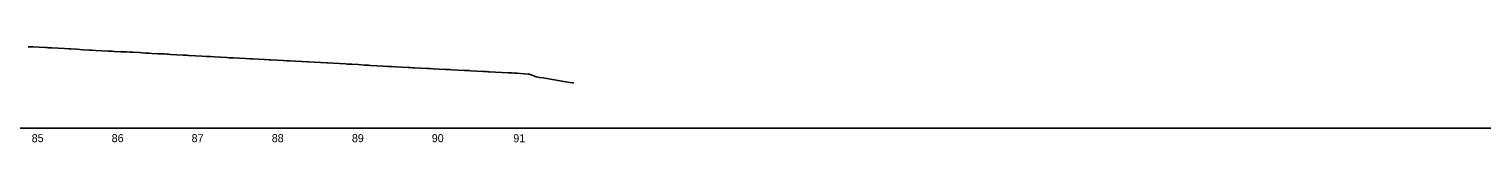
# Model space of a CAD drawing. Extents: x 579185 to 595036, y -53221 to -44640.
# Drawn here: x 586699 to 588514, y -46055 to -45936 of the extents above; entities that cross this region are included whole.
import ezdxf

# ---------------------------------------------------------------- set-up
doc = ezdxf.new("R2010")
doc.units = 0
for name, color, linetype in [('Exist Profile Cell', 7, 'Continuous'), ('Exist Vertical Profile Ground Line', 7, 'Continuous'), ('Exist Vertical Profile Horizontal Axis Label Major', 7, 'Continuous')]:
    doc.layers.add(name, color=color, linetype=linetype)

msp = doc.modelspace()

# ---------------------------------------------------------------- linework, layer by layer
at = {"layer": 'Exist Profile Cell'}
msp.add_line((579243, -46037.5), (595036.4, -46037.5), dxfattribs=at)
at = {"layer": 'Exist Vertical Profile Ground Line'}
for points in [[(586697.6, -45935.8), (586703.7, -45936.1), (586711.5, -45936.5), (586719.3, -45936.9), (586721.2, -45937), (586722.9, -45937.1), (586724.6, -45937.2), (586727.1, -45937.3), (586735, -45937.7), (586742.8, -45938.2), (586748.6, -45938.5), (586750.9, -45938.6), (586758.4, -45939), (586766.2, -45939.5), (586774.2, -45940), (586777.3, -45940.1), (586781.8, -45940.4), (586789.6, -45940.8), (586797.4, -45941.2), (586799.3, -45941.3), (586802.7, -45941.5), (586805.2, -45941.6), (586813, -45942), (586820.9, -45942.4), (586824.5, -45942.6), (586827.8, -45942.8), (586828.7, -45942.8), (586836.5, -45943.2), (586844.3, -45943.7), (586848.6, -45943.9), (586852.1, -45944.1), (586859.9, -45944.5), (586867.7, -45944.9), (586870.8, -45945.1), (586872.7, -45945.2), (586875.5, -45945.4), (586883.3, -45945.8), (586891.1, -45946.3), (586895.6, -45946.5), (586897.7, -45946.7), (586898.9, -45946.7), (586906.8, -45947.2), (586914.6, -45947.6), (586920.2, -45947.9), (586922.7, -45948.1), (586925.3, -45948.2), (586930.2, -45948.5), (586938, -45948.9), (586945.8, -45949.3), (586948.6, -45949.5), (586951.7, -45949.7), (586953.6, -45949.8), (586961.4, -45950.2), (586969.2, -45950.6), (586974.5, -45950.8), (586977, -45951)], [(586977, -45951), (586977.8, -45951), (586984.9, -45951.4), (586992.7, -45951.8), (586998.8, -45952.1), (587000.5, -45952.2), (587008.3, -45952.6), (587016.1, -45953), (587020.9, -45953.3), (587023, -45953.4), (587023.9, -45953.4), (587031.7, -45953.9), (587039.5, -45954.3), (587046.5, -45954.6), (587047.3, -45954.7), (587047.7, -45954.7), (587055.1, -45955.1), (587062.9, -45955.5), (587070.8, -45955.9), (587071.7, -45956), (587072.5, -45956), (587078.6, -45956.4), (587086.4, -45956.8), (587094.2, -45957.3), (587096.2, -45957.4), (587097.6, -45957.5), (587102, -45957.8), (587109.8, -45958.2), (587117.6, -45958.7), (587120.6, -45958.9), (587122.8, -45959), (587125.4, -45959.2), (587133.2, -45959.6), (587141, -45960), (587146.4, -45960.4), (587148.9, -45960.5), (587151.5, -45960.6), (587156.7, -45960.9), (587164.5, -45961.3), (587172.3, -45961.8), (587175.1, -45961.9), (587177.7, -45962.1), (587180.1, -45962.2), (587187.9, -45962.5), (587195.7, -45962.9), (587199.9, -45963.1), (587203.5, -45963.3), (587211.3, -45963.7), (587219.1, -45964.1), (587222.7, -45964.2), (587224.7, -45964.3), (587226.9, -45964.5), (587234.8, -45964.9), (587242.6, -45965.4), (587246.6, -45965.6), (587248.5, -45965.7), (587250.4, -45965.8), (587258.2, -45966.2), (587266, -45966.7), (587270.3, -45966.9), (587272.4, -45967.1), (587273.8, -45967.1), (587281.6, -45967.5), (587289.4, -45967.9), (587297.2, -45968.3), (587299.8, -45968.5), (587302.4, -45968.6), (587305, -45968.7), (587306.8, -45968.8), (587308.7, -45968.9), (587312.8, -45969.2), (587317.5, -45969.5), (587322.2, -45969.9), (587323.9, -45970), (587326.9, -45971.2), (587331.6, -45973.1), (587332.2, -45973.4), (587336.3, -45974.1), (587341, -45974.8), (587345.7, -45975.6), (587350.3, -45976.4), (587355, -45977.2), (587359.7, -45978), (587364.4, -45978.7), (587369.1, -45979.5), (587373.8, -45980.3), (587378.5, -45981.1), (587379.2, -45981.2)]]:
    msp.add_lwpolyline(points, dxfattribs=at)

# ---------------------------------------------------------------- texts
at = {"layer": 'Exist Vertical Profile Horizontal Axis Label Major'}
for s, p in [('85', (586702, -46055)), ('86', (586801.9, -46055)), ('87', (586901.8, -46055)), ('88', (587001.9, -46055)), ('89', (587102, -46055)), ('90', (587201.8, -46055)), ('91', (587303.7, -46055))]:
    msp.add_text(s, height=10, dxfattribs=at).set_placement(p)

doc.saveas('drawing.dxf')
